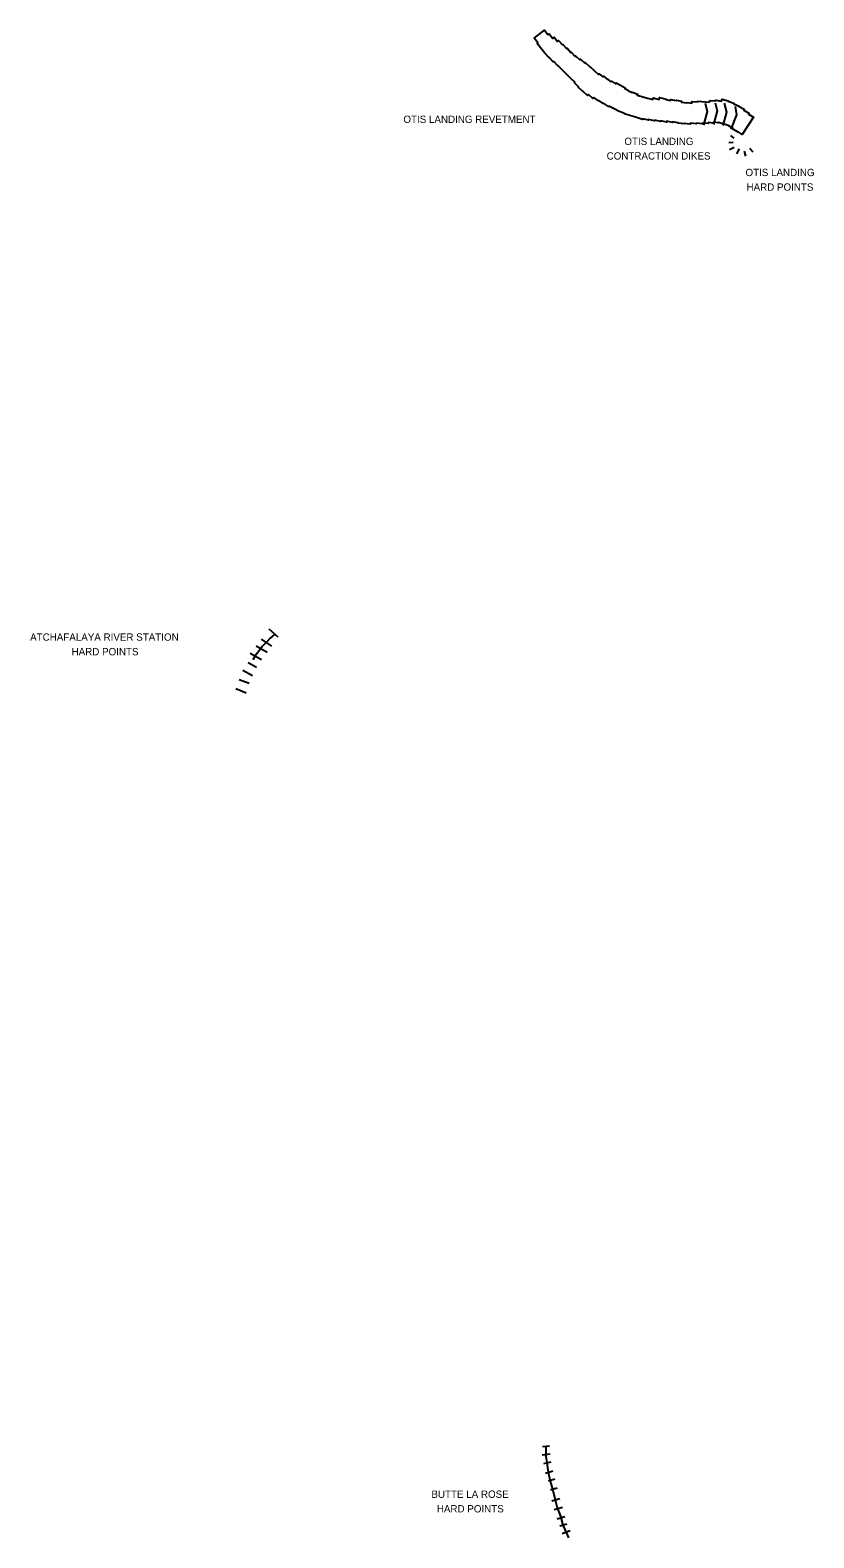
# Model space of a CAD drawing. Extents: x 2650582 to 3923188, y 277893 to 989177.
# Drawn here: x 3155873 to 3173000, y 658088 to 691042 of the extents above; entities that cross this region are included whole.
import ezdxf

# ---------------------------------------------------------------- set-up
doc = ezdxf.new("R2010")
doc.units = 0
doc.layers.add('Level 3', color=7, linetype='Continuous')

msp = doc.modelspace()

# ---------------------------------------------------------------- linework, layer by layer
at = {"layer": 'Level 3'}
for p, q in [((3171181, 688737), (3171248, 688681)), ((3171141, 688585), (3171236, 688592)), ((3171159, 688437), (3171260, 688484)), ((3171318, 688342), (3171375, 688451)), ((3171677, 688375), (3171599, 688456)), ((3171511, 688289), (3171487, 688400)), ((3161088, 677954), (3161287, 677780)), ((3160813, 677582), (3161053, 677450)), ((3160923, 677734), (3161151, 677581)), ((3160639, 677220), (3160821, 677119)), ((3160679, 677427), (3160928, 677290)), ((3160521, 677056), (3160735, 676938)), ((3160370, 676654), (3160591, 676560)), ((3160660, 676759), (3160440, 676844)), ((3167068, 660084), (3167224, 660097)), ((3167063, 659904), (3167240, 659927)), ((3167102, 659714), (3167261, 659747)), ((3167132, 659505), (3167298, 659552)), ((3167198, 659335), (3167342, 659375)), ((3167245, 659140), (3167390, 659180)), ((3167277, 658900), (3167451, 658949)), ((3167328, 658710), (3167506, 658760)), ((3167389, 658507), (3167556, 658554)), ((3167450, 658350), (3167605, 658394)), ((3167500, 658181), (3167675, 658251))]:
    msp.add_line(p, q, dxfattribs=at)
for points in [[(3168864, 689218), (3168751, 689267), (3168748, 689261), (3168635, 689319), (3168521, 689383), (3168515, 689374), (3168402, 689443), (3168399, 689439), (3168301, 689505), (3168295, 689497), (3168192, 689573), (3168173, 689550), (3168074, 689633), (3168057, 689614), (3167957, 689703), (3167953, 689698), (3167850, 689794), (3167860, 689804), (3167766, 689893), (3167777, 689905), (3167692, 689984), (3167691, 689983), (3167588, 690084), (3167589, 690085), (3167523, 690150), (3167412, 690264), (3167407, 690260), (3167318, 690360), (3167304, 690349), (3167217, 690448), (3167211, 690443), (3167124, 690541), (3167120, 690537), (3167030, 690646), (3167035, 690650), (3166952, 690752), (3166965, 690762), (3166885, 690865), (3167113, 691042), (3167189, 690944), (3167213, 690963), (3167293, 690863), (3167323, 690888), (3167399, 690796), (3167421, 690816), (3167505, 690721), (3167515, 690729), (3167599, 690634), (3167612, 690645), (3167692, 690555), (3167696, 690559), (3167783, 690469), (3167794, 690480), (3167883, 690391), (3167903, 690411), (3167990, 690325), (3168001, 690337), (3168100, 690246), (3168103, 690249), (3168291, 690072), (3168308, 690091), (3168386, 690021), (3168401, 690037), (3168488, 689964), (3168493, 689970), (3168566, 689916), (3168580, 689928), (3168668, 689869), (3168682, 689891), (3168771, 689837), (3168774, 689842), (3168876, 689785), (3168866, 689767), (3168953, 689723), (3168949, 689715), (3169030, 689680), (3169033, 689688), (3169150, 689645), (3169142, 689623), (3169244, 689591), (3169244, 689593), (3169368, 689555), (3169483, 689529), (3169490, 689560), (3169619, 689529), (3169629, 689569), (3169769, 689535), (3169767, 689528), (3169870, 689502), (3169876, 689528), (3169993, 689503), (3169997, 689512), (3170109, 689490), (3170105, 689470), (3170221, 689450), (3170222, 689458), (3170330, 689449), (3170334, 689485), (3170464, 689473), (3170465, 689489), (3170718, 689469)], [(3170718, 689469), (3170728, 689506), (3170850, 689494), (3170857, 689513), (3170985, 689492), (3170996, 689531), (3171130, 689496), (3171128, 689490), (3171253, 689448), (3171248, 689433), (3171370, 689383), (3171365, 689371), (3171479, 689312), (3171471, 689296), (3171587, 689228), (3171574, 689207), (3171678, 689139), (3171434, 688765), (3171347, 688821), (3171343, 688815), (3171222, 688887), (3171229, 688898), (3171144, 688943), (3171149, 688954), (3171019, 688998), (3170910, 689026), (3170908, 689014), (3170811, 689029), (3170809, 689012), (3170695, 689024), (3170694, 689001), (3170563, 689012), (3170562, 688996), (3170436, 689006)], [(3170626, 689447), (3170672, 689266), (3170586, 688964)], [(3170842, 689456), (3170889, 689282), (3170808, 688978)], [(3171038, 689446), (3171089, 689247), (3171008, 688958)], [(3170436, 689006), (3170434, 688994), (3170302, 689007), (3170300, 688987), (3170169, 688999), (3170169, 688995), (3170033, 689011), (3170034, 689014), (3169914, 689037), (3169912, 689027), (3169787, 689053), (3169781, 689028), (3169654, 689060), (3169650, 689047), (3169522, 689078), (3169517, 689058), (3169389, 689089), (3169385, 689072), (3169260, 689101), (3169256, 689089), (3169100, 689137), (3169001, 689167), (3168863, 689216), (3168864, 689218)], [(3171283, 689375), (3171310, 689190), (3171185, 688876)], [(3161222, 677837), (3161116, 677756), (3161047, 677676), (3160954, 677575), (3160915, 677525), (3160847, 677443), (3160789, 677367), (3160741, 677278)], [(3167140, 660090), (3167143, 659876), (3167164, 659726), (3167192, 659522), (3167235, 659328), (3167294, 659133), (3167347, 658916), (3167390, 658745), (3167461, 658559), (3167512, 658367), (3167596, 658189), (3167637, 658088)]]:
    msp.add_lwpolyline(points, dxfattribs=at)

# ---------------------------------------------------------------- texts
for s, p in [('OTIS LANDING REVETMENT', (3164030, 689014)), ('OTIS LANDING', (3168859, 688532)), ('CONTRACTION DIKES', (3168472, 688213)), ('OTIS LANDING', (3171506, 687852)), ('HARD POINTS', (3171529, 687533)), ('ATCHAFALAYA RIVER STATION', (3155873, 677697)), ('HARD POINTS', (3156779, 677378)), ('BUTTE LA ROSE', (3164643, 658963)), ('HARD POINTS', (3164761, 658644))]:
    msp.add_text(s, height=160, dxfattribs=at).set_placement(p)

doc.saveas('drawing.dxf')
